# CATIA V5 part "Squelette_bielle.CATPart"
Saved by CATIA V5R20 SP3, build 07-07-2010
Part number: Squelette_bielle
Publications: "Droite.2", "Point.2", "Point.1", "Droite.1", "Droite.3", "Plan.1"
Bounding box of the stored display mesh (mm): x -10 to 10, y 0 to 8, z 0 to 0
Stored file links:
  C:\Documents and Settings\Propriétaire\Mes documents\IFMA\COURS\PROJ IAO\CATIA\Squelette_bielle.CATPart
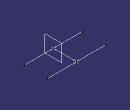
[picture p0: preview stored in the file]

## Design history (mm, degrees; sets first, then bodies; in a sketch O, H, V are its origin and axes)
Set1
  Plane1: type Offset, RefPlane yz-plane, Offset 0
  Point1: (0, 0, 0)
  Line1: type Normal, RefPoint Point1, RefSkin Plane1, Start -10, End 10
  Point2: (0, 8, 0)
  Line2: type PtDir, RefPoint Point2, Direction Plane1, Start -10, End 10
  Line3: type PtPt, FirstPoint Point2, SecondPoint Point1
Body1 (main body)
